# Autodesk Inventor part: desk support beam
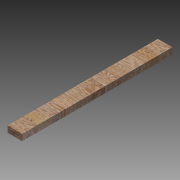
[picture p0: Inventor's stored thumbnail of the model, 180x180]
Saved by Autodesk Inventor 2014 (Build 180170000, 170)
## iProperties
Created: 2013-07
Part Number: desk support beam
Material: Generic
Document SubType Name: Modeling
Designer: Patrick Rice
Density: 1 g/cm^3
Appearance: Red Oak - Natural
Author: Patrick Rice
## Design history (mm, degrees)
sketch "Sketch1"
  geometry: L1 (44.45, -19.05)-(-44.45, -19.05); L2 (-44.45, -19.05)-(-44.45, 19.05); L3 (-44.45, 19.05)-(44.45, 19.05); L4 (44.45, 19.05)-(44.45, -19.05); L5 (44.45, -19.05)-(-44.45, 19.05); L6 (-44.45, -19.05)-(44.45, 19.05); 1 further point
  constraints: 12 end point, 2 midpoint, 2 parallel, 1 horizontal, 1 perpendicular
  dimensions: "d0" = 38.1 distance of L1.end L2.end; "d1" = 88.9 distance of L2.end L3.end
extrude "Extrusion1" new body sketch "Sketch1" distance "d2" = 914.4; taper "d3" = 0 deg
hole "Hole1" diameter "d6" = 6.35; stored, may be unused: countersink angle "d10" = 82 deg, drill point angle "d12" = 118 deg; dims "d4" = 101.6, "d5" = 44.45, "d7" = 19.05, "d8" = 19.05, "d9" = 12.7, "d11" = 25.4
hole "Hole2" diameter "d15" = 6.35; stored, may be unused: countersink angle "d19" = 82 deg, drill point angle "d21" = 118 deg; dims "d13" = 44.45, "d14" = 101.6, "d16" = 19.05, "d17" = 19.05, "d18" = 12.7, "d20" = 25.4
body "Solid1"
